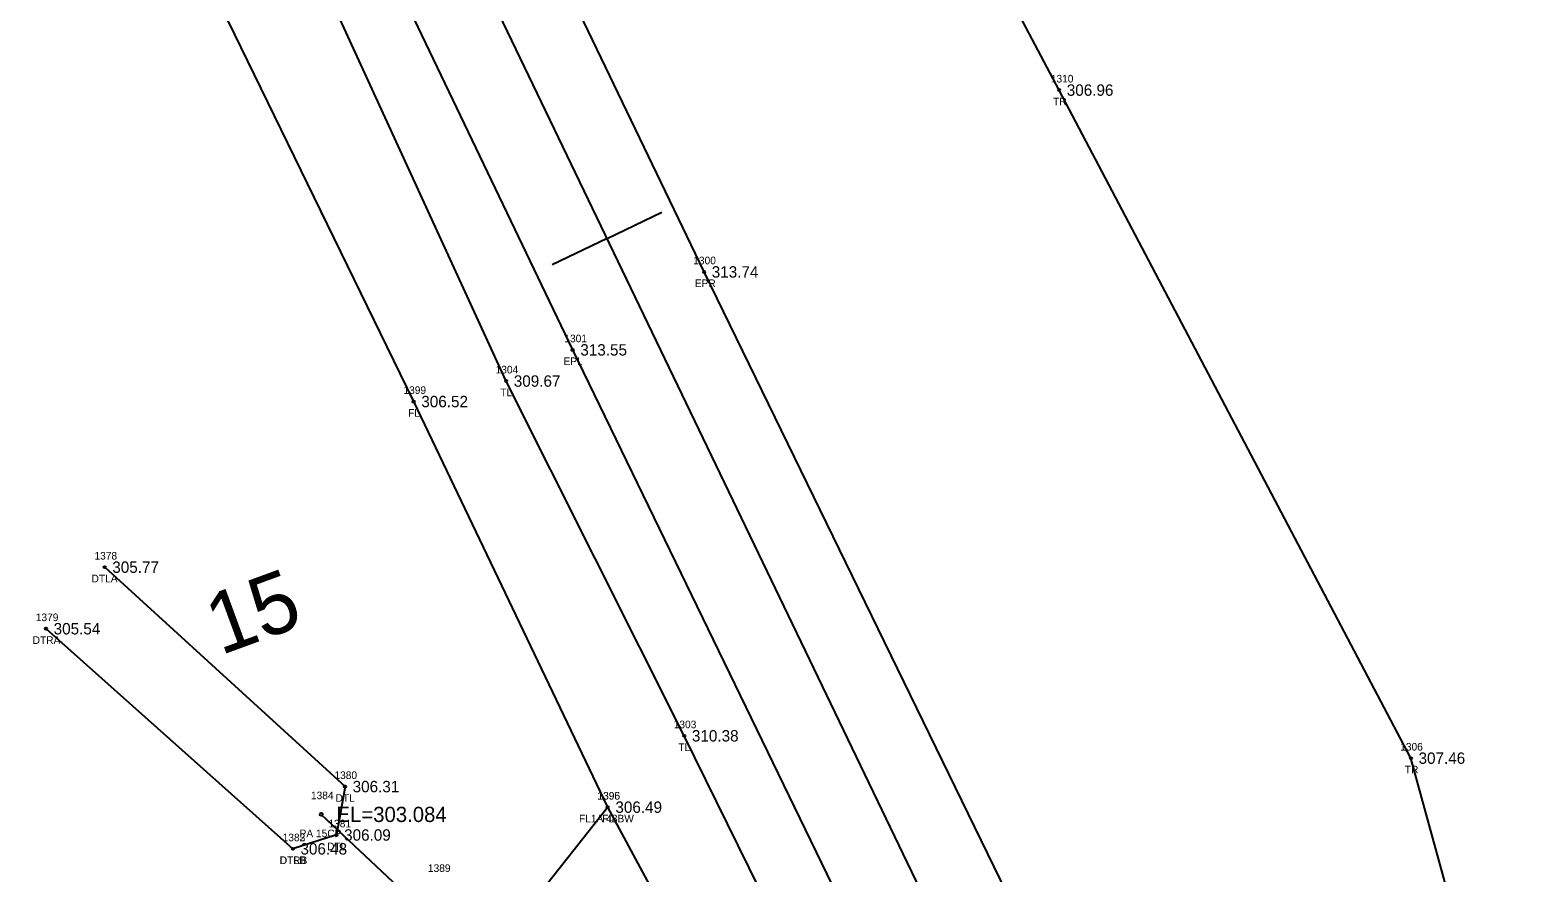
# Model space of a CAD drawing. Extents: x 1865045 to 1867370, y 910391 to 914218.
# Drawn here: x 1866241.8 to 1866440, y 911134.6 to 911245.5 of the extents above; entities that cross this region are included whole.
import ezdxf

# ---------------------------------------------------------------- set-up
doc = ezdxf.new("R2010")
doc.units = 0
for name, color, linetype in [('RD_EX_DR_Pipe', 7, 'Continuous'), ('RD_EX_DR_Pipe_txCode', 7, 'Continuous'), ('RD_EX_Fence_Other', 7, 'Continuous'), ('RD_EX_Fence_Other_txCode', 7, 'Continuous'), ('RD_EX_H2O', 7, 'Continuous'), ('RD_EX_H2O_txCode', 7, 'Continuous'), ('RD_EX_Road', 7, 'Continuous'), ('RD_EX_Road_txCode', 7, 'Continuous'), ('RD_EX_TX_Fence_Other_ELEV', 7, 'Continuous'), ('RD_EX_TX_H2O_ELEV', 7, 'Continuous'), ('RD_EX_TX_Road_ELEV', 7, 'Continuous'), ('RD_EX_TX_VEG_ELEV', 7, 'Continuous'), ('RD_EX_VEG', 7, 'Continuous'), ('RD_EX_VEG_txCode', 7, 'Continuous'), ('RD_HC_Cl', 7, 'Continuous'), ('RD_HC_Data_Tic', 7, 'Continuous'), ('RD_HC_TX_Sta50', 7, 'Continuous'), ('RD_SMD_Locator', 7, 'Continuous'), ('RD_TX_Pipe_ElevEX', 7, 'Continuous')]:
    doc.layers.add(name, color=color, linetype=linetype)

msp = doc.modelspace()

# ---------------------------------------------------------------- linework, layer by layer
at = {"layer": 'RD_EX_DR_Pipe'}
msp.add_line((1866280.05, 911142.32), (1866293.34, 911129.82), dxfattribs=at)
at = {"layer": 'RD_EX_Fence_Other'}
for points in [[(1866328.11, 911123.98), (1866317.73, 911143.27), (1866292.21, 911196.64), (1866254.72, 911273.66), (1866198.8, 911388.88), (1866160.41, 911467.37), (1866132.32, 911522.75), (1866123.76, 911516.89), (1866120.96, 911520.71)], [(1866317.73, 911143.27), (1866280.58, 911096.16), (1866262.33, 911070.09)]]:
    msp.add_lwpolyline(points, dxfattribs=at)
at = {"layer": 'RD_EX_H2O'}
msp.add_line((1866243.87, 911166.75), (1866276.32, 911137.79), dxfattribs=at)
msp.add_lwpolyline([(1866251.58, 911174.85), (1866283.18, 911145.98), (1866282.06, 911139.61), (1866276.32, 911137.79)], dxfattribs=at)
at = {"layer": 'RD_EX_Road'}
for points in [[(1866367.09, 911115.22), (1866376.17, 911119.76), (1866330.4, 911213.7), (1866286.92, 911304.16), (1866242.4, 911396.3), (1866197.74, 911488.67), (1866154.31, 911579.91), (1866143.08, 911603.17), (1866108.16, 911674.25), (1866059.64, 911774.84), (1866048.38, 911798.67), (1866045.99, 911803.62)], [(1866367.09, 911115.22), (1866357.99, 911110.97), (1866313.12, 911203.44), (1866268.86, 911295.9), (1866224.24, 911388.66), (1866179.87, 911480.6), (1866149.84, 911543.41), (1866142.18, 911559.37), (1866135.93, 911572.05), (1866096.83, 911651.51), (1866089.65, 911665.46), (1866062.87, 911720.39), (1866042.14, 911765.69), (1866027.93, 911795.04)]]:
    msp.add_lwpolyline(points, dxfattribs=at)
at = {"layer": 'RD_EX_VEG'}
for points in [[(1866452.86, 910898.44), (1866327.79, 911152.66), (1866304.37, 911199.34), (1866261.27, 911293.31), (1866216.38, 911387.21), (1866171.77, 911477.63), (1866125.33, 911567.24), (1866081.32, 911550.6)], [(1866477.92, 910951.04), (1866423.33, 911149.72), (1866377.08, 911237.62), (1866329.48, 911327.65), (1866279.59, 911419.45), (1866252.34, 911486.96)]]:
    msp.add_lwpolyline(points, dxfattribs=at)
at = {"layer": 'RD_HC_Cl'}
msp.add_line((1866502.49, 910833.56), (1866280.52, 911295.32), dxfattribs=at)
at = {"layer": 'RD_HC_Data_Tic'}
for q in [(1866324.85, 911221.57), (1866310.43, 911214.64)]:
    msp.add_line((1866317.64, 911218.1), q, dxfattribs=at)
at = {"layer": 'RD_SMD_Locator'}
for centre, radius in [((1866377.08, 911237.62), 0.15), ((1866330.4, 911213.7), 0.15), ((1866313.12, 911203.44), 0.15), ((1866304.37, 911199.34), 0.15), ((1866292.21, 911196.64), 0.15), ((1866251.58, 911174.85), 0.15), ((1866243.87, 911166.75), 0.15), ((1866327.79, 911152.66), 0.15), ((1866423.33, 911149.72), 0.15), ((1866283.18, 911145.98), 0.15), ((1866280.05, 911142.32), 0.2), ((1866317.73, 911143.27), 0.15), ((1866317.73, 911143.27), 0.15), ((1866282.06, 911139.61), 0.15), ((1866276.32, 911137.79), 0.15), ((1866276.32, 911137.79), 0.15)]:
    msp.add_circle(centre, radius, dxfattribs=at)

# ---------------------------------------------------------------- texts
at = {"layer": 'RD_EX_DR_Pipe_txCode'}
for s, p in [('1384', (1866278.7, 911144.32)), ('PA 15CP', (1866277.21, 911139.32))]:
    msp.add_text(s, height=1, dxfattribs=at).set_placement(p)
at = {"layer": 'RD_EX_Fence_Other_txCode'}
for s, p in [('1399', (1866290.86, 911197.64)), ('FL', (1866291.47, 911194.64)), ('1396', (1866316.36, 911144.27)), ('1395', (1866316.38, 911144.27)), ('FL1A 48BW', (1866313.95, 911141.27)), ('FL', (1866317, 911141.27))]:
    msp.add_text(s, height=1, dxfattribs=at).set_placement(p)
at = {"layer": 'RD_EX_H2O_txCode'}
for s, p in [('1378', (1866250.24, 911175.85)), ('DTLA', (1866249.85, 911172.85)), ('1379', (1866242.52, 911167.75)), ('DTRA', (1866242.11, 911164.75)), ('1380', (1866281.79, 911146.98)), ('DTL', (1866281.93, 911143.98)), ('1382', (1866274.98, 911138.79)), ('1383', (1866274.98, 911138.79)), ('1381', (1866281, 911140.61)), ('DTL', (1866280.82, 911137.61)), ('DTRB', (1866274.58, 911135.79)), ('DTLB', (1866274.61, 911135.79)), ('1389', (1866294.08, 911134.75))]:
    msp.add_text(s, height=1, dxfattribs=at).set_placement(p)
at = {"layer": 'RD_EX_Road_txCode'}
for s, p in [('1300', (1866328.97, 911214.7)), ('EPR', (1866329.17, 911211.7)), ('1301', (1866312.02, 911204.44)), ('EPL', (1866311.91, 911201.44))]:
    msp.add_text(s, height=1, dxfattribs=at).set_placement(p)
at = {"layer": 'RD_EX_TX_Fence_Other_ELEV'}
for s, p in [('306.52', (1866293.21, 911195.89)), ('306.49', (1866318.73, 911142.52)), ('306.49', (1866318.73, 911142.52))]:
    msp.add_text(s, height=1.5, dxfattribs=at).set_placement(p)
at = {"layer": 'RD_EX_TX_H2O_ELEV'}
for s, p in [('305.77', (1866252.58, 911174.1)), ('305.54', (1866244.87, 911166)), ('306.31', (1866284.18, 911145.23)), ('306.09', (1866283.06, 911138.86)), ('306.48', (1866277.32, 911137.04)), ('306.48', (1866277.32, 911137.04))]:
    msp.add_text(s, height=1.5, dxfattribs=at).set_placement(p)
at = {"layer": 'RD_EX_TX_Road_ELEV'}
for s, p in [('313.74', (1866331.4, 911212.95)), ('313.55', (1866314.12, 911202.69))]:
    msp.add_text(s, height=1.5, dxfattribs=at).set_placement(p)
at = {"layer": 'RD_EX_TX_VEG_ELEV'}
for s, p in [('306.96', (1866378.08, 911236.87)), ('309.67', (1866305.37, 911198.59)), ('310.38', (1866328.79, 911151.91)), ('307.46', (1866424.33, 911148.97))]:
    msp.add_text(s, height=1.5, dxfattribs=at).set_placement(p)
at = {"layer": 'RD_EX_VEG_txCode'}
for s, p in [('1310', (1866375.98, 911238.62)), ('TR', (1866376.28, 911235.62)), ('1304', (1866302.98, 911200.34)), ('TL', (1866303.59, 911197.34)), ('1303', (1866326.4, 911153.66)), ('TL', (1866327.02, 911150.66)), ('1306', (1866421.92, 911150.72)), ('TR', (1866422.53, 911147.72))]:
    msp.add_text(s, height=1, dxfattribs=at).set_placement(p)
at = {"layer": 'RD_HC_TX_Sta50'}
msp.add_text('15', height=8, rotation=20.1386, dxfattribs=at).set_placement((1866266.81, 911163.22))
at = {"layer": 'RD_TX_Pipe_ElevEX'}
msp.add_text('EL=303.084', height=2, dxfattribs=at).set_placement((1866282.05, 911141.32))

doc.saveas('drawing.dxf')
